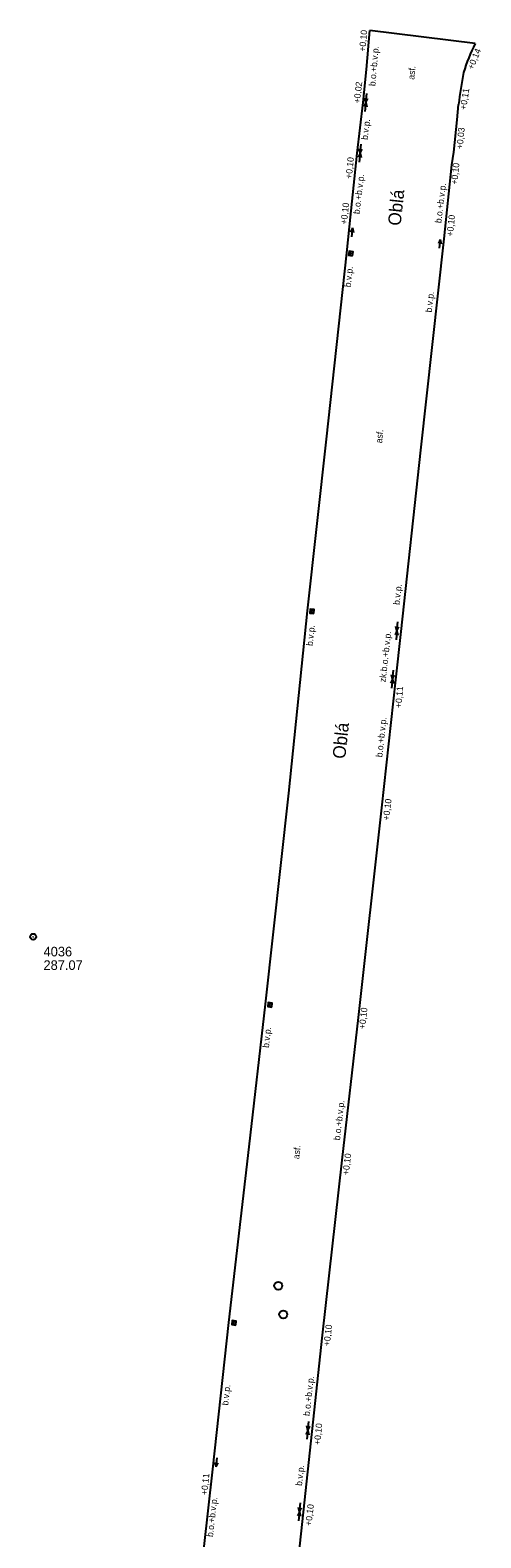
# Model space of a CAD drawing. Extents: x -602107 to -602012, y -1162711 to -1162518.
# Drawn here: x -602040.2 to -602012, y -1162612.4 to -1162518.3 of the extents above; entities that cross this region are included whole.
import ezdxf

# ---------------------------------------------------------------- set-up
doc = ezdxf.new("R2010")
doc.units = 0
for name, color, linetype in [('Vrstva 2', 7, 'Continuous'), ('Vrstva 25', 7, 'Continuous'), ('Vrstva 42', 7, 'Continuous'), ('Vrstva 49', 7, 'Continuous'), ('Vrstva 50', 7, 'Continuous'), ('Vrstva 63', 7, 'Continuous'), ('Vrstva 7', 7, 'Continuous')]:
    doc.layers.add(name, color=color, linetype=linetype)

msp = doc.modelspace()

# ---------------------------------------------------------------- linework, layer by layer
at = {"layer": 'Vrstva 2'}
for radius in [0.188, 0.00025]:
    msp.add_circle((-602039.97, -1162574.9), radius, dxfattribs=at)
at = {"layer": 'Vrstva 25'}
for p, q in [((-602020.128, -1162532.362), (-602020.097, -1162532.114)), ((-602022.561, -1162554.715), (-602022.539, -1162554.465)), ((-602025.184, -1162579.274), (-602025.156, -1162579.026)), ((-602027.436, -1162599.134), (-602027.404, -1162598.886))]:
    msp.add_line(p, q, dxfattribs=at)
for points in [[(-602020.003, -1162532.378), (-602019.972, -1162532.13), (-602020.221, -1162532.099), (-602020.252, -1162532.347)], [(-602022.435, -1162554.726), (-602022.414, -1162554.477), (-602022.664, -1162554.455), (-602022.685, -1162554.704)], [(-602025.059, -1162579.289), (-602025.031, -1162579.04), (-602025.28, -1162579.012), (-602025.308, -1162579.26)], [(-602027.311, -1162599.15), (-602027.279, -1162598.902), (-602027.528, -1162598.87), (-602027.56, -1162599.118)]]:
    msp.add_lwpolyline(points, close=True, dxfattribs=at)
for centre in [(-602024.65, -1162596.69), (-602024.34, -1162598.48)]:
    msp.add_circle(centre, 0.25, dxfattribs=at)
at = {"layer": 'Vrstva 49'}
for p, q in [((-602019.183, -1162522.81), (-602019.304, -1162523.065)), ((-602019.183, -1162522.81), (-602019.246, -1162523.366)), ((-602019.183, -1162522.81), (-602019.244, -1162522.534)), ((-602019.183, -1162522.81), (-602019.119, -1162522.254)), ((-602019.183, -1162522.81), (-602019.061, -1162522.555)), ((-602019.183, -1162522.81), (-602019.121, -1162523.086)), ((-602019.533, -1162525.98), (-602019.596, -1162525.705)), ((-602019.533, -1162525.98), (-602019.472, -1162525.423)), ((-602019.533, -1162525.98), (-602019.413, -1162525.725)), ((-602019.533, -1162525.98), (-602019.653, -1162526.235)), ((-602019.533, -1162525.98), (-602019.594, -1162526.537)), ((-602019.533, -1162525.98), (-602019.47, -1162526.255)), ((-602020.017, -1162530.65), (-602020.137, -1162530.905)), ((-602020.017, -1162530.65), (-602020.078, -1162531.207)), ((-602020.017, -1162530.65), (-602019.954, -1162530.925)), ((-602014.524, -1162531.363), (-602014.645, -1162531.618)), ((-602014.524, -1162531.363), (-602014.585, -1162531.919)), ((-602014.524, -1162531.363), (-602014.462, -1162531.638)), ((-602017.232, -1162555.801), (-602017.352, -1162556.056)), ((-602017.232, -1162555.801), (-602017.294, -1162555.526)), ((-602017.232, -1162555.801), (-602017.292, -1162556.358)), ((-602017.232, -1162555.801), (-602017.171, -1162555.244)), ((-602017.232, -1162555.801), (-602017.111, -1162555.545)), ((-602017.232, -1162555.801), (-602017.169, -1162556.076)), ((-602017.512, -1162558.823), (-602017.574, -1162558.547)), ((-602017.512, -1162558.823), (-602017.451, -1162558.266)), ((-602017.512, -1162558.823), (-602017.391, -1162558.567)), ((-602017.512, -1162558.823), (-602017.632, -1162559.078)), ((-602017.512, -1162558.823), (-602017.572, -1162559.379)), ((-602017.512, -1162558.823), (-602017.449, -1162559.098)), ((-602022.803, -1162605.724), (-602022.923, -1162605.98)), ((-602022.803, -1162605.724), (-602022.865, -1162605.449)), ((-602022.803, -1162605.724), (-602022.863, -1162606.281)), ((-602022.803, -1162605.724), (-602022.742, -1162605.167)), ((-602022.803, -1162605.724), (-602022.682, -1162605.469)), ((-602022.803, -1162605.724), (-602022.74, -1162605.999)), ((-602028.527, -1162607.998), (-602028.466, -1162607.441)), ((-602028.527, -1162607.998), (-602028.589, -1162607.722)), ((-602028.527, -1162607.998), (-602028.406, -1162607.742)), ((-602023.327, -1162610.807), (-602023.267, -1162610.251)), ((-602023.327, -1162610.807), (-602023.448, -1162611.063)), ((-602023.327, -1162610.807), (-602023.39, -1162610.532)), ((-602023.327, -1162610.807), (-602023.388, -1162611.364)), ((-602023.327, -1162610.807), (-602023.207, -1162610.552)), ((-602023.327, -1162610.807), (-602023.265, -1162611.083))]:
    msp.add_line(p, q, dxfattribs=at)
at = {"layer": 'Vrstva 63'}
msp.add_lwpolyline([(-602012.35, -1162519.13), (-602018.92, -1162518.31)], dxfattribs=at)
at = {"layer": 'Vrstva 7'}
for points in [[(-602019.34, -1162522.81), (-602019.13, -1162520.75), (-602018.92, -1162518.31)], [(-602019.71, -1162525.98), (-602019.34, -1162522.81)], [(-602014.29, -1162531.32), (-602013.8, -1162526.71), (-602013.68, -1162525.91), (-602013.48, -1162523.9), (-602013.38, -1162522.93)], [(-602020.19, -1162530.57), (-602019.71, -1162525.98)], [(-602028.75, -1162608.15), (-602027.73, -1162598.98), (-602026.46, -1162588.02), (-602025.45, -1162579.12), (-602024, -1162565.94), (-602022.82, -1162554.56), (-602021.63, -1162543.84), (-602020.36, -1162532.2), (-602020.19, -1162530.57)], [(-602016.98, -1162555.84), (-602015.75, -1162544.52), (-602014.29, -1162531.32)], [(-602017.3, -1162558.87), (-602016.98, -1162555.84)], [(-602022.53, -1162605.79), (-602021.88, -1162599.78), (-602020.66, -1162588.86), (-602019.64, -1162579.94), (-602018.17, -1162566.86), (-602017.3, -1162558.87)], [(-602023.08, -1162610.83), (-602022.53, -1162605.79)], [(-602029.6, -1162615.92), (-602029.31, -1162613.17), (-602028.75, -1162608.15)], [(-602024.97, -1162628.98), (-602024.9, -1162627.99), (-602024.77, -1162626.31), (-602024.52, -1162623.96), (-602024.45, -1162623.4), (-602024.4, -1162622.99), (-602024.17, -1162620.91), (-602024.11, -1162620.38), (-602024.05, -1162619.91), (-602023.08, -1162610.83)]]:
    msp.add_lwpolyline(points, dxfattribs=at)
for centre, radius, start, end in [((-602002.3, -1162524.158), 11.238, 153.42025, 163.41181), ((-601985.246, -1162526.321), 28.338, 169.07522, 173.12815)]:
    msp.add_arc(centre, radius, start, end, dxfattribs=at)

# ---------------------------------------------------------------- texts
at = {"layer": 'Vrstva 2'}
for s, p in [('4036', (-602039.318, -1162576.129)), ('287.07', (-602039.323, -1162576.974))]:
    msp.add_text(s, height=0.6, dxfattribs=at).set_placement(p)
at = {"layer": 'Vrstva 42'}
for p in [(-602017.007, -1162530.539), (-602020.467, -1162563.822)]:
    msp.add_text('Oblá', height=0.8, rotation=83.90732, dxfattribs=at).set_placement(p)
at = {"layer": 'Vrstva 49'}
for s, rotation, p in [('b.o.+b.v.p.', 84.91924, (-602018.588, -1162521.805)), ('asf.', 84.51605, (-602016.15, -1162521.4)), ('b.v.p.', 82.98303, (-602019.069, -1162525.165)), ('b.o.+b.v.p.', 83.09305, (-602019.577, -1162529.801)), ('b.o.+b.v.p.', 83.09305, (-602014.466, -1162530.365)), ('b.v.p.', 83.67706, (-602020.127, -1162534.364)), ('b.v.p.', 83.67706, (-602015.059, -1162535.937)), ('asf.', 84.51605, (-602018.166, -1162544.106)), ('b.v.p.', 83.67706, (-602017.075, -1162554.198)), ('b.v.p.', 83.67706, (-602022.504, -1162556.76)), ('zk.b.o.+b.v.p.', 83.67706, (-602017.944, -1162559.028)), ('b.o.+b.v.p.', 83.67706, (-602018.155, -1162563.711)), ('b.v.p.', 83.67706, (-602025.239, -1162581.855)), ('b.o.+b.v.p.', 83.67706, (-602020.792, -1162587.631)), ('asf.', 84.51605, (-602023.34, -1162588.8)), ('b.v.p.', 83.67706, (-602027.783, -1162604.182)), ('b.o.+b.v.p.', 83.67706, (-602022.694, -1162604.842)), ('b.v.p.', 83.67706, (-602023.17, -1162609.204)), ('b.o.+b.v.p.', 83.67706, (-602028.731, -1162612.395))]:
    msp.add_text(s, height=0.4, rotation=rotation, dxfattribs=at).set_placement(p)
at = {"layer": 'Vrstva 50'}
for s, rotation, p in [('+0,10', 85.16877, (-602019.203, -1162519.651)), ('+0,14', 67.9103, (-602012.473, -1162520.794)), ('+0,02', 83.67641, (-602019.547, -1162522.882)), ('+0,11', 81.19603, (-602012.912, -1162523.293)), ('+0,03', 84.57476, (-602013.126, -1162525.739)), ('+0,10', 83.93153, (-602020.06, -1162527.593)), ('+0,10', 84.04243, (-602013.467, -1162527.953)), ('+0,10', 83.76218, (-602020.366, -1162530.441)), ('+0,10', 84.04243, (-602013.738, -1162531.194)), ('+0,11', 85.32891, (-602016.952, -1162560.635)), ('+0,10', 83.23033, (-602017.724, -1162567.658)), ('+0,10', 83.52906, (-602019.225, -1162580.689)), ('+0,10', 83.51232, (-602020.244, -1162589.797)), ('+0,10', 83.66397, (-602021.434, -1162600.482)), ('+0,10', 84.41118, (-602022.03, -1162606.645)), ('+0,11', 84.21954, (-602029.087, -1162609.777)), ('+0,10', 83.51614, (-602022.575, -1162611.698))]:
    msp.add_text(s, height=0.4, rotation=rotation, dxfattribs=at).set_placement(p)

doc.saveas('drawing.dxf')
